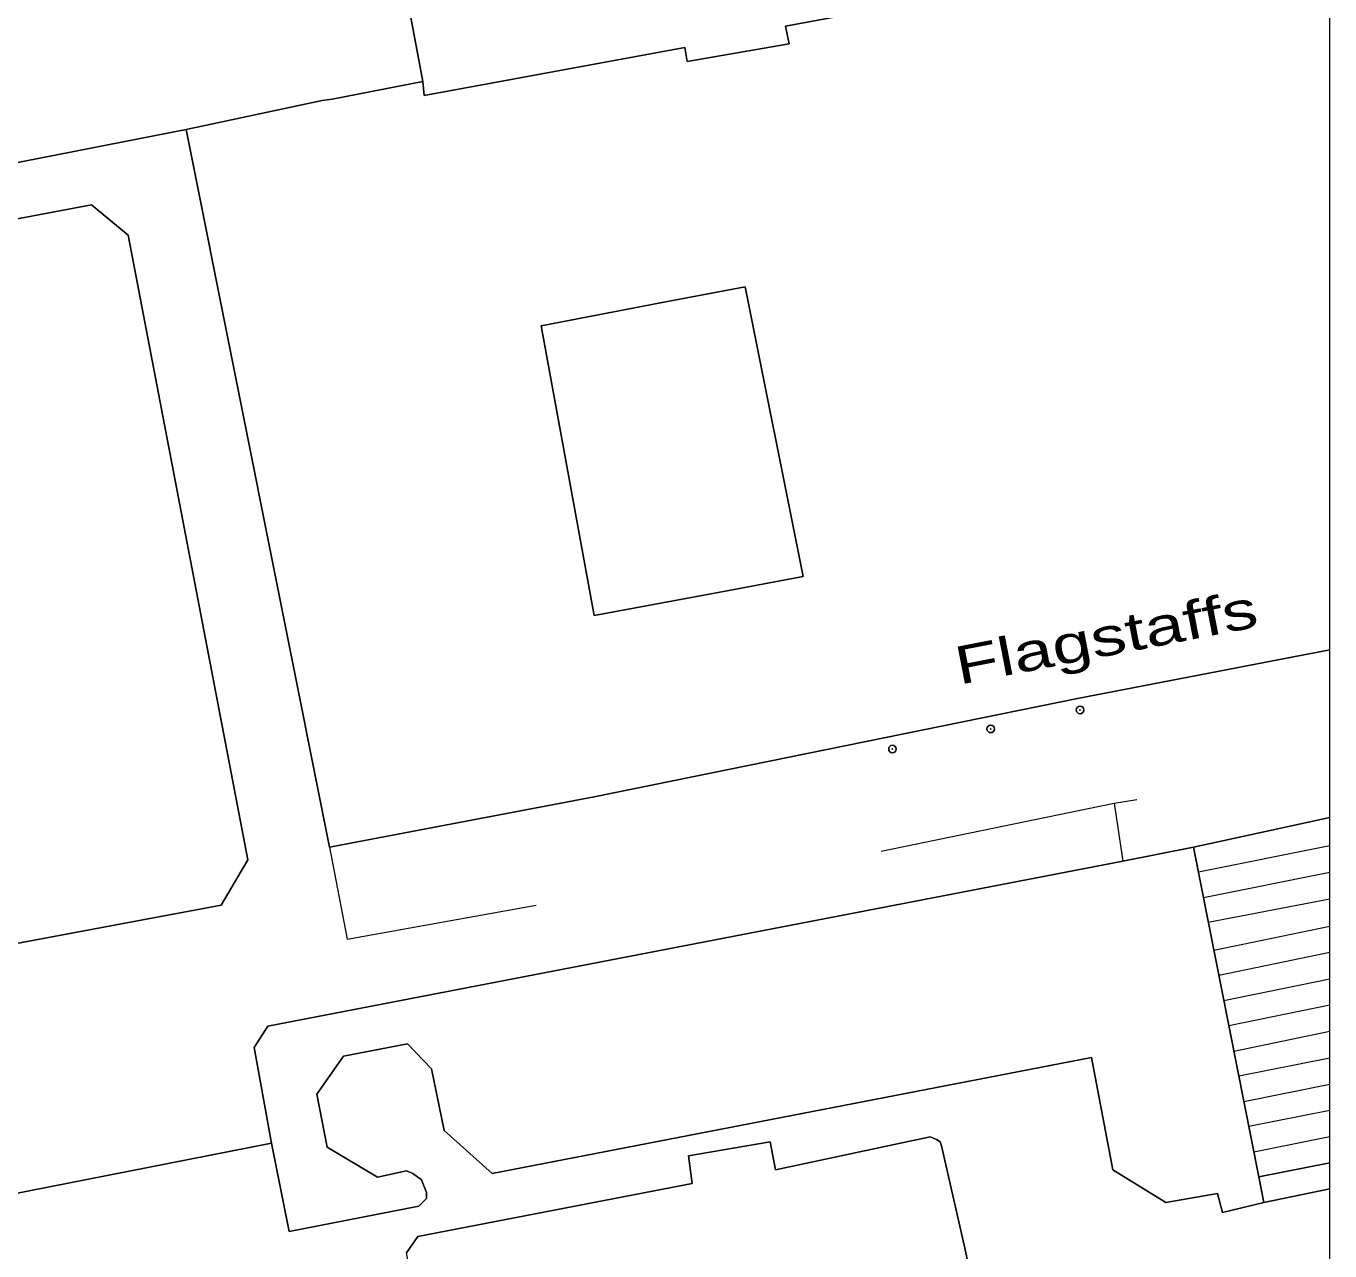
# Model space of a CAD drawing. Extents: x 528790 to 529292, y 179350 to 179856.
# Drawn here: x 529238.4 to 529290.2, y 179510.4 to 179559 of the extents above; entities that cross this region are included whole.
import ezdxf

# ---------------------------------------------------------------- set-up
doc = ezdxf.new("R2010")
doc.units = 0
doc.header["$LTSCALE"] = 0.6
doc.header["$PDMODE"] = 32
doc.header["$PDSIZE"] = 0.3
for name, color, linetype, lineweight in [('1', 7, 'Continuous', 13), ('2', 7, 'Continuous', 13), ('7', 7, 'Continuous', 13)]:
    doc.layers.add(name, color=color, linetype=linetype, lineweight=lineweight)
doc.layers.add('3', color=7, linetype='Continuous')
doc.layers.add('5', color=7, linetype='Continuous')

msp = doc.modelspace()

# ---------------------------------------------------------------- linework, layer by layer
at = {"layer": '1'}
for points in [[(529272.4, 179559.7), (529268.6, 179559), (529268.75, 179558.3), (529264.7, 179557.6), (529264.6, 179558.15), (529254.25, 179556.25), (529254.2, 179556.8), (529250.6, 179556.1), (529250.2, 179556.05), (529244.8, 179554.9), (529250.5, 179526.4), (529261, 179528.4), (529280.2, 179532.3), (529290.22, 179534.231), (529290.22, 179571.313)], [(529230, 179552), (529244.8, 179554.9), (529250.2, 179556.05), (529250.6, 179556.1), (529254.2, 179556.8), (529252.8, 179564.3)], [(529235.2, 179512.1), (529248.2, 179514.65), (529247.5, 179518.45), (529248.05, 179519.3), (529282, 179525.85), (529284.8, 179526.4), (529290.22, 179527.576), (529290.22, 179534.231), (529280.2, 179532.3), (529261, 179528.4), (529250.5, 179526.4), (529244.8, 179554.9), (529230, 179552)], [(529230.45, 179549.9), (529241.05, 179551.9), (529242.5, 179550.7), (529247.25, 179525.9), (529246.2, 179524.1), (529231.2, 179521.3)], [(529290.22, 179487.963), (529290.22, 179512.837), (529287.6, 179512.3), (529285.95, 179511.9), (529285.75, 179512.65), (529283.7, 179512.3), (529281.6, 179513.6), (529280.75, 179518.05), (529256.95, 179513.45), (529255.05, 179515.15), (529254.55, 179517.6), (529253.6, 179518.6), (529251.05, 179518.1), (529250, 179516.6), (529250.4, 179514.5), (529252.4, 179513.3), (529253.55, 179513.55), (529253.8, 179513.45), (529254.15, 179513.2), (529254.35, 179512.7), (529254.35, 179512.45), (529254.05, 179512.15), (529248.9, 179511.15), (529248.2, 179514.65), (529235.2, 179512.1)], [(529253.55, 179510.3), (529254, 179510.95), (529264.9, 179513.05), (529264.75, 179514.15), (529268, 179514.7), (529268.2, 179513.6), (529274.35, 179514.9), (529274.6, 179514.8), (529274.75, 179514.7), (529274.8, 179514.55), (529275.7, 179510.6), (529276.3, 179507.8)], [(529276.3, 179507.8), (529275.7, 179510.6), (529274.8, 179514.55), (529274.75, 179514.7), (529274.6, 179514.8), (529274.35, 179514.9), (529268.2, 179513.6), (529268, 179514.7), (529264.75, 179514.15), (529264.9, 179513.05), (529254, 179510.95), (529253.55, 179510.3)]]:
    msp.add_lwpolyline(points, dxfattribs=at)
for points in [[(529272.2, 179560.5), (529271.1, 179566.85), (529270.95, 179567.7), (529267.15, 179567), (529267, 179567.3), (529264.95, 179566.95), (529263.1, 179566.65), (529263.15, 179566.25), (529252.8, 179564.3), (529254.2, 179556.8), (529254.25, 179556.25), (529264.6, 179558.15), (529264.7, 179557.6), (529268.75, 179558.3), (529268.6, 179559), (529272.4, 179559.7)], [(529231.2, 179521.3), (529246.2, 179524.1), (529247.25, 179525.9), (529242.5, 179550.7), (529241.05, 179551.9), (529230.45, 179549.9), (529218.75, 179547.6), (529208.5, 179545.65), (529207.5, 179544.55), (529209.8, 179532.4), (529212.15, 179520.05), (529212.4, 179518.65), (529213.5, 179518.05), (529214.748, 179518.273), (529217.4, 179518.75), (529218.844, 179519.016), (529228.8, 179520.85)], [(529261, 179535.6), (529265.925, 179536.52), (529269.3, 179537.15), (529267, 179548.65), (529263.707, 179548.02), (529258.9, 179547.1)], [(529258.9, 179547.1), (529263.707, 179548.02), (529267, 179548.65), (529269.3, 179537.15), (529265.925, 179536.52), (529261, 179535.6)], [(529290.22, 179527.576), (529284.8, 179526.4), (529287.4, 179513.31), (529290.22, 179513.873)], [(529287.6, 179512.3), (529287.4, 179513.31), (529284.8, 179526.4), (529282, 179525.85), (529248.05, 179519.3), (529247.5, 179518.45), (529248.2, 179514.65), (529248.9, 179511.15), (529254.05, 179512.15), (529254.35, 179512.45), (529254.35, 179512.7), (529254.15, 179513.2), (529253.8, 179513.45), (529253.55, 179513.55), (529252.4, 179513.3), (529250.4, 179514.5), (529250, 179516.6), (529251.05, 179518.1), (529253.6, 179518.6), (529254.55, 179517.6), (529255.05, 179515.15), (529256.95, 179513.45), (529280.75, 179518.05), (529281.6, 179513.6), (529283.7, 179512.3), (529285.75, 179512.65), (529285.95, 179511.9)], [(529290.22, 179512.837), (529290.22, 179513.873), (529287.4, 179513.31), (529287.6, 179512.3)]]:
    msp.add_lwpolyline(points, close=True, dxfattribs=at)
at = {"layer": '2'}
for p, q in [((529254.2, 179556.8), (529250.6, 179556.1)), ((529244.8, 179554.9), (529230, 179552)), ((529244.8, 179554.9), (529250.5, 179526.4)), ((529272.4, 179526.25), (529281.65, 179528.15)), ((529281.65, 179528.15), (529282.55, 179528.3)), ((529281.65, 179528.15), (529282, 179525.85)), ((529284.8, 179526.4), (529290.22, 179527.576)), ((529284.8, 179526.4), (529282, 179525.85)), ((529287.4, 179513.31), (529284.8, 179526.4)), ((529290.22, 179526.452), (529285, 179525.41)), ((529285.2, 179524.41), (529290.22, 179525.412)), ((529290.22, 179524.343), (529285.39, 179523.41)), ((529285.61, 179522.31), (529290.22, 179523.264)), ((529290.22, 179522.217), (529285.81, 179521.31)), ((529286.01, 179520.31), (529290.22, 179521.177)), ((529290.22, 179520.135), (529286.21, 179519.31)), ((529286.41, 179518.31), (529290.22, 179519.095)), ((529290.22, 179518.032), (529286.6, 179517.31)), ((529286.8, 179516.31), (529290.22, 179516.993)), ((529290.22, 179515.953), (529287, 179515.31)), ((529287.2, 179514.31), (529290.22, 179514.913)), ((529290.22, 179513.873), (529287.4, 179513.31)), ((529287.6, 179512.3), (529287.4, 179513.31)), ((529290.22, 179512.837), (529287.6, 179512.3))]:
    msp.add_line(p, q, dxfattribs=at)
for points in [[(529254.2, 179556.8), (529252.8, 179564.3), (529263.15, 179566.25), (529263.1, 179566.65), (529264.95, 179566.95)], [(529272.2, 179560.5), (529272.4, 179559.7), (529268.6, 179559), (529268.75, 179558.3), (529264.7, 179557.6), (529264.6, 179558.15), (529254.25, 179556.25), (529254.2, 179556.8)], [(529250.6, 179556.1), (529250.2, 179556.05), (529244.8, 179554.9)], [(529230.45, 179549.9), (529241.05, 179551.9), (529242.5, 179550.7), (529247.25, 179525.9), (529246.2, 179524.1), (529231.2, 179521.3)], [(529263.707, 179548.02), (529267, 179548.65), (529269.3, 179537.15), (529265.925, 179536.52)], [(529265.925, 179536.52), (529261, 179535.6), (529258.9, 179547.1), (529263.707, 179548.02)], [(529250.5, 179526.4), (529261, 179528.4), (529280.2, 179532.3), (529290.22, 179534.231)], [(529250.5, 179526.4), (529251.2, 179522.75), (529258.7, 179524.1)], [(529282, 179525.85), (529248.05, 179519.3), (529247.5, 179518.45), (529248.2, 179514.65)], [(529254.05, 179512.15), (529254.35, 179512.45), (529254.35, 179512.7), (529254.15, 179513.2), (529253.8, 179513.45), (529253.55, 179513.55), (529252.4, 179513.3), (529250.4, 179514.5), (529250, 179516.6), (529251.05, 179518.1), (529253.6, 179518.6), (529254.55, 179517.6), (529255.05, 179515.15), (529256.95, 179513.45), (529280.75, 179518.05)], [(529280.75, 179518.05), (529281.6, 179513.6), (529283.7, 179512.3), (529285.75, 179512.65), (529285.95, 179511.9), (529287.6, 179512.3)], [(529236.8, 179503.2), (529235.2, 179512.1), (529248.2, 179514.65)], [(529248.2, 179514.65), (529248.9, 179511.15), (529254.05, 179512.15)], [(529254.2, 179506.8), (529253.55, 179510.3), (529254, 179510.95), (529264.9, 179513.05), (529264.75, 179514.15), (529268, 179514.7), (529268.2, 179513.6), (529274.35, 179514.9), (529274.6, 179514.8), (529274.75, 179514.7), (529274.8, 179514.55), (529275.7, 179510.6), (529276.3, 179507.8)]]:
    msp.add_lwpolyline(points, dxfattribs=at)
at = {"layer": '3'}
for p in [(529280.3, 179531.85), (529276.75, 179531.1), (529272.85, 179530.3)]:
    msp.add_point(p, dxfattribs=at)
at = {"layer": '7'}
msp.add_lwpolyline([(528790.22, 179356.024), (529290.22, 179356.024), (529290.22, 179856.024), (528790.22, 179856.024)], close=True, dxfattribs=at)

# ---------------------------------------------------------------- texts
at = {"layer": '5', "width": 1.4}
msp.add_text('Flagstaffs', height=1.5, rotation=11, dxfattribs=at).set_placement((529275.5, 179532.85))

doc.saveas('drawing.dxf')
